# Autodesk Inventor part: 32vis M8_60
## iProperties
Created: 2011-01
Part Number: 32vis M8_60
Document SubType Name: Modeling
Designer: eric
Density: 1 g/cm^3
Mass: 3.87317 g
Surface Area: 22.0249 cm^2
Volume: 3.87317 cm^3
Author: eric
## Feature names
1. Base1
